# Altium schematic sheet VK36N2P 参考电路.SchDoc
size A4
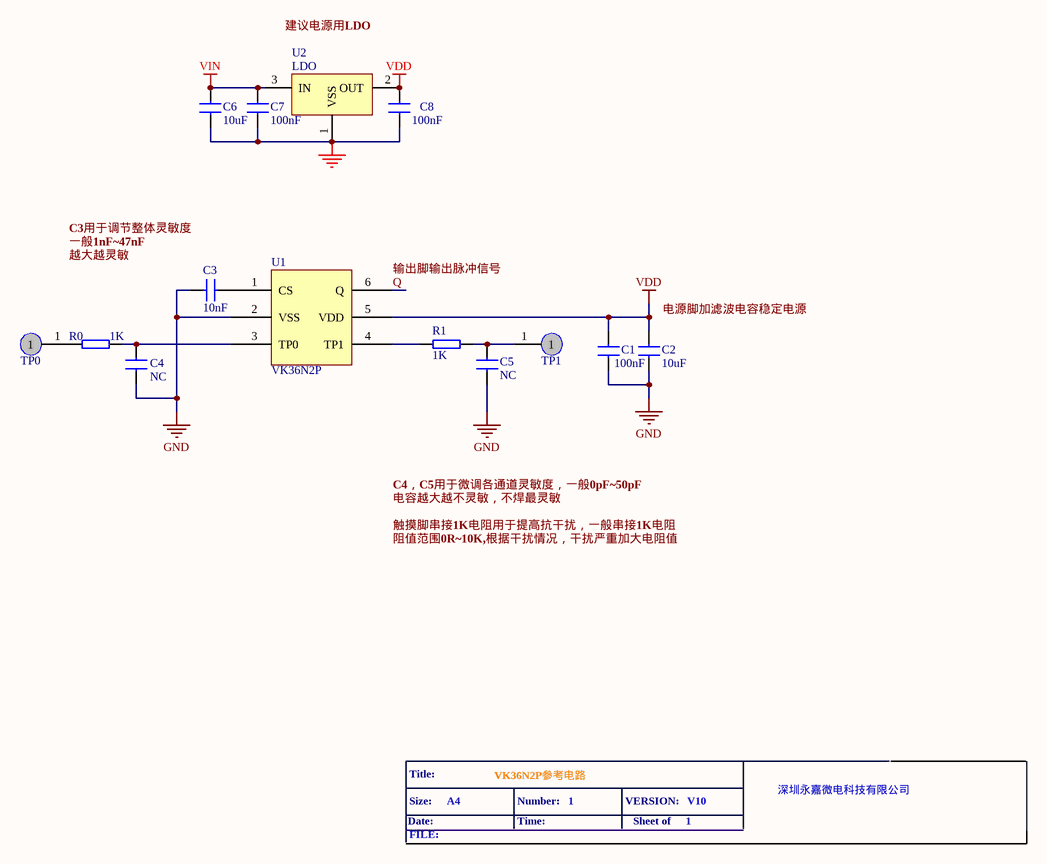
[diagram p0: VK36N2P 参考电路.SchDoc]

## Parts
C1  100nF  [0603-C]
C2  10uF  [0603-C]
C3  value 10nF  [0603-C]  (hidden comment: 10uF)
C4  value NC  [0603-C]  (hidden comment: 10uF)
C5  value NC  [0603-C]  (hidden comment: 10uF)
C6  10uF  [0805-C]
C7  100nF  [0805-C]
C8  100nF  [0805-C]
R0  1K  [0603-R]
R1  1K  [0603-R]
TP0  TPAD  [TP-PAD0]  (value not drawn)
TP1  TPAD  [TP-PAD0]  (value not drawn)
U1  VK36N2P
U2  LDO  [SOT-23]

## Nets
GND: C1.2 C2.2 C3.2 C4.1 C5.1 C6.2 C7.2 C8.2 U1.2(VSS) U2.1(VSS)
VDD: C1.1 C2.1 C8.1 U1.5(VDD) U2.2(OUT)
VIN: C6.1 C7.1 U2.3(IN)
Q: U1.6(Q)
NetC3_1: C3.1 U1.1(CS)
NetC4_2: C4.2 R0.1 U1.3(TP0)
NetC5_2: C5.2 R1.1 TP1.1
NetR0_2: R0.2 TP0.1
NetR1_2: R1.2 U1.4(TP1)

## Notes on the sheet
- 建议电源用LDO
- C3用于调节整体灵敏度
- 一般1nF~47nF
- 越大越灵敏
- 输出脚输出脉冲信号
- (near C2) 电源脚加滤波电容稳定电源
- C4，C5用于微调各通道灵敏度，一般0pF~50pF
- 触摸脚串接1K电阻用于提高抗干扰，一般串接1K电阻
- 阻值范围0R
  0K,根据干扰情况，干扰严重加大电阻值
- 电容越大越不灵敏，不焊最灵敏
- Date:
- Title:
- Size:
- A4
- VK36N2P参考电路
- Number:
- Time:
- 1
- VERSION:
- Sheet of
- V10
- 深圳永嘉微电科技有限公司
- FILE:

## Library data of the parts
C1-C8 = CAP: Capacitor
R0 R1 = RES: Resistor
TP0 TP1 = TPAD: TESTING
U2 = V6206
